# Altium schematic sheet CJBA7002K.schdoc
size 127 x 101 mm
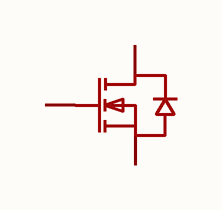
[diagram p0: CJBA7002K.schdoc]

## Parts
Q?  cjba7002k  [DFN1006-3L_L1.0-W0.6-BL]  (value not drawn)

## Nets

Not connected (* = marked no-connect by the designer): Q? 1(S) 2(D) 3(G)

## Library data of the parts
Q? = cjba7002k: 数量:1个N沟道;漏源电压(Vdss):60V;连续漏极电流(Id):410mA;导通电阻(RDS(on)):1.8Ω@4.5V;耗散功率(Pd):100mW;阈值电压(Vgs(th)):1.4V;; Manufacturer: CJ(江苏长电/长晶); AddInBom: yes; ModelId: 89988d492fd24034894d084d947c97a1; ModelName: DFN1006-3L_L1.0-W0.6-H0.4-BL; ModelTransform: 39.764,24.0157,0,0,0,0,0,0,0; Number: 1个N沟道; Drain to Source Voltage: 60V; Current - Continuous Drain(Id): 410mA; Pd - Power Dissipation: 100mW; Gate Threshold Voltage (Vgs(th)): 1.4V; Gate Charge(Qg): 2.8nC@10V; Input Capacitance(Ciss): 80pF; Reverse Transfer Capacitance (Crss@Vds): 5.6pF; Type: N沟道; Output Capacitance(Coss): 3.6pF; Vgs: ±20V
